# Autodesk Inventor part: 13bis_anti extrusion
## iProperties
Created: 2000-12
Part Number: 13bis_anti extrusion
Material: Par défaut
Document SubType Name: Modélisation
Designer: Administrateur
Control State: 0
Master: False
Checked Out: False
Shininess: 20.0
Length Units: 11269
Angle Units: 11279
Time Units: 11290
Mass Units: 11283
Length Display Precision: 3
Angle Display Precision: 2
Density: 0.0
Volumn: 0.0
Area: 0.0
PropertySet Name: Model Information
Author: Administrateur
